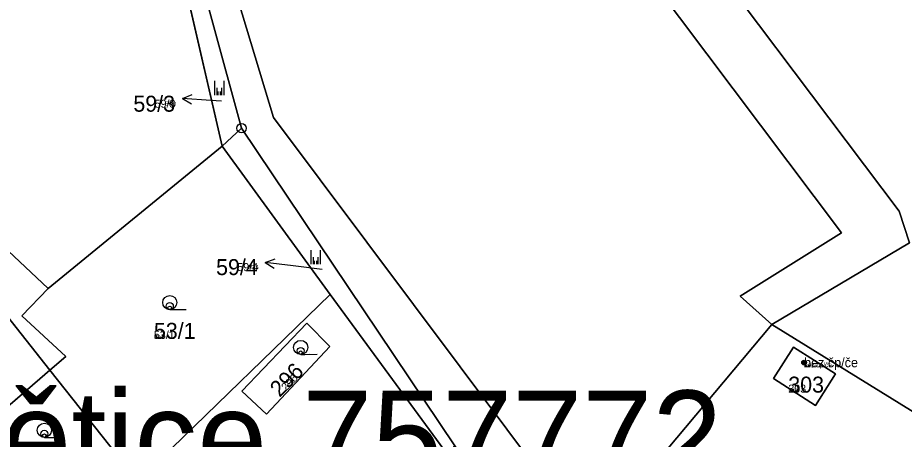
# Model space of a CAD drawing. Extents: x -759873 to -758487, y -975024 to -973516.
# Drawn here: x -759094.4 to -759000.3, y -974305.6 to -974260.8 of the extents above; entities that cross this region are included whole.
import ezdxf

# ---------------------------------------------------------------- set-up
doc = ezdxf.new("R2010")
doc.units = 0
for name, color, linetype in [('KAT_02_hranice parcel', 7, 'Continuous'), ('KAT_03_1000_st čísla parcelní', 7, 'Continuous'), ('KAT_03_1000_čísla parcelní', 7, 'Continuous'), ('KAT_03_1000_čísla popisná', 7, 'Continuous'), ('KAT_03_250_st čísla parcelní', 7, 'Continuous'), ('KAT_03_250_čísla parcelní', 7, 'Continuous'), ('KAT_03_250_čísla popisná', 7, 'Continuous'), ('KAT_03_500_st čísla parcelní', 7, 'Continuous'), ('KAT_03_500_čísla parcelní', 7, 'Continuous'), ('KAT_03_500_čísla popisná', 7, 'Continuous'), ('KAT_05_1000_značky kultur', 7, 'Continuous'), ('KAT_05_250_značky kultur', 7, 'Continuous'), ('KAT_05_500_značky kultur', 7, 'Continuous'), ('KAT_07_1000_značky budov', 7, 'Continuous'), ('KAT_07_250_značky budov', 7, 'Continuous'), ('KAT_07_500_značky budov', 7, 'Continuous'), ('KAT_11_značky bodu BP', 7, 'Continuous'), ('KAT_12_pomocná šipka', 7, 'Continuous'), ('KAT_13_popis', 7, 'Continuous'), ('KAT_14_plocha_budovy', 7, 'Continuous'), ('KAT_14_plocha_pozemek', 7, 'Continuous')]:
    doc.layers.add(name, color=color, linetype=linetype)

msp = doc.modelspace()

# ---------------------------------------------------------------- linework, layer by layer
at = {"layer": 'KAT_02_hranice parcel'}
for p, q in [((-759072.72, -974274.42), (-759081.12, -974237.92)), ((-759072.72, -974274.42), (-759070.66, -974272.52)), ((-759070.66, -974272.52), (-759048.01, -974306.32)), ((-759091.19, -974289.59), (-759072.72, -974274.42)), ((-759061.26, -974290.22), (-759072.72, -974274.42)), ((-759091.02, -974298.25), (-759100.58, -974286.17)), ((-759061.26, -974290.22), (-759079.26, -974307.73)), ((-759048.78, -974307.23), (-759061.26, -974290.22)), ((-759014.33, -974293.41), (-758997.18, -974304.01)), ((-759098.18, -974304.42), (-759091.02, -974298.25)), ((-759083.84, -974307.33), (-759091.02, -974298.25))]:
    msp.add_line(p, q, dxfattribs=at)
for points in [[(-759057.23, -974110.82), (-759070.93, -974124.94), (-759074.88, -974130.5), (-759080.81, -974167.04), (-759083.49, -974196.85), (-759080.01, -974222.92), (-759077.81, -974236.38), (-759067.25, -974271.4), (-759032.56, -974317.79)], [(-759057.23, -974110.82), (-759060.75, -974132.98), (-759061.42, -974162.34), (-759060.12, -974196.25), (-759049.48, -974222.24), (-759032.75, -974249.27), (-759006.93, -974283.66), (-759017.69, -974290.39), (-759014.33, -974293.41)], [(-759081.12, -974237.92), (-759079.79, -974238.96), (-759070.66, -974272.52)], [(-759033.4, -974238.15), (-759026.91, -974246.64), (-759000.81, -974281.35), (-758999.72, -974284.7), (-759014.33, -974293.41)], [(-759123.38, -974266.06), (-759120.2, -974262.27), (-759091.19, -974289.59)], [(-759091.19, -974289.59), (-759093.99, -974292.47), (-759089.32, -974296.79), (-759091.02, -974298.25)], [(-759061.29, -974295.76), (-759068, -974302.93), (-759070.62, -974300.51), (-759063.73, -974293.25), (-759061.29, -974295.76)], [(-759014.33, -974293.41), (-759025.5, -974306.76), (-759032.56, -974317.79)], [(-759007.55, -974298.66), (-759009.69, -974302.02), (-759014.16, -974299.16), (-759012.02, -974295.81), (-759007.55, -974298.66)]]:
    msp.add_lwpolyline(points, dxfattribs=at)
at = {"layer": 'KAT_03_1000_čísla popisná'}
msp.add_circle((-759010.9, -974297.45), 0.25, dxfattribs=at)
at = {"layer": 'KAT_03_250_čísla popisná'}
msp.add_circle((-759010.9, -974297.45), 0.0625, dxfattribs=at)
at = {"layer": 'KAT_03_500_čísla popisná'}
msp.add_circle((-759010.9, -974297.45), 0.125, dxfattribs=at)
at = {"layer": 'KAT_05_1000_značky kultur'}
for p, q in [((-759073.511, -974268.99), (-759073.511, -974267.49)), ((-759072.51, -974268.99), (-759072.51, -974267.49)), ((-759063.281, -974287), (-759063.281, -974285.5)), ((-759062.28, -974287), (-759062.28, -974285.5)), ((-759078.283, -974291.82), (-759076.533, -974291.82)), ((-759064.363, -974296.59), (-759062.613, -974296.559)), ((-759091.603, -974305.41), (-759089.853, -974305.41))]:
    msp.add_line(p, q, dxfattribs=at)
for centre in [(-759078.283, -974291.07), (-759064.376, -974295.84), (-759091.603, -974304.66)]:
    msp.add_circle(centre, 0.75, dxfattribs=at)
at = {"layer": 'KAT_05_250_značky kultur'}
for p, q in [((-759073.128, -974268.99), (-759073.128, -974268.615)), ((-759072.878, -974268.99), (-759072.878, -974268.615)), ((-759062.898, -974287), (-759062.898, -974286.625)), ((-759062.647, -974287), (-759062.647, -974286.625)), ((-759078.288, -974291.82), (-759077.851, -974291.82)), ((-759064.368, -974296.59), (-759063.931, -974296.582)), ((-759091.608, -974305.41), (-759091.171, -974305.41))]:
    msp.add_line(p, q, dxfattribs=at)
for centre in [(-759078.288, -974291.632), (-759064.371, -974296.402), (-759091.608, -974305.222)]:
    msp.add_circle(centre, 0.187, dxfattribs=at)
at = {"layer": 'KAT_05_500_značky kultur'}
for p, q in [((-759073.255, -974268.99), (-759073.255, -974268.24)), ((-759072.755, -974268.99), (-759072.755, -974268.24)), ((-759063.025, -974287), (-759063.025, -974286.25)), ((-759062.525, -974287), (-759062.525, -974286.25)), ((-759078.287, -974291.82), (-759077.412, -974291.82)), ((-759064.367, -974296.59), (-759063.492, -974296.574)), ((-759091.606, -974305.41), (-759090.731, -974305.41))]:
    msp.add_line(p, q, dxfattribs=at)
for centre in [(-759078.286, -974291.445), (-759064.373, -974296.215), (-759091.606, -974305.035)]:
    msp.add_circle(centre, 0.375, dxfattribs=at)
at = {"layer": 'KAT_07_1000_značky budov'}
msp.add_circle((-759010.907, -974297.449), 0.175, dxfattribs=at)
at = {"layer": 'KAT_07_250_značky budov'}
msp.add_circle((-759010.902, -974297.45), 0.0437, dxfattribs=at)
at = {"layer": 'KAT_07_500_značky budov'}
msp.add_circle((-759010.903, -974297.45), 0.0875, dxfattribs=at)
at = {"layer": 'KAT_11_značky bodu BP'}
for radius in [0.5, 0.0303]:
    msp.add_circle((-759070.66, -974272.52), radius, dxfattribs=at)
at = {"layer": 'KAT_12_pomocná šipka'}
for p, q in [((-759076.924, -974269.371), (-759075.89, -974268.941)), ((-759073.93, -974269.58), (-759076.924, -974269.371)), ((-759076.924, -974269.371), (-759075.96, -974269.94)), ((-759072.79, -974269.66), (-759073.93, -974269.58)), ((-759068.139, -974286.804), (-759067.084, -974286.429)), ((-759065.16, -974287.17), (-759068.139, -974286.804)), ((-759068.139, -974286.804), (-759067.206, -974287.423)), ((-759062.09, -974287.54), (-759065.16, -974287.17))]:
    msp.add_line(p, q, dxfattribs=at)
at = {"layer": 'KAT_14_plocha_budovy'}
msp.add_lwpolyline([(-759014.16, -974299.16), (-759009.69, -974302.02), (-759007.55, -974298.66), (-759012.02, -974295.81)], close=True, dxfattribs=at)
at = {"layer": 'KAT_14_plocha_pozemek'}
for points in [[(-758984.12, -974076.91), (-759010.79, -974116.64), (-759007.07, -974119.22), (-759009.9, -974123.16), (-759045.17, -974103.85), (-759057.23, -974110.82), (-759057.79, -974134.47), (-759058.26, -974162.28), (-759056.91, -974183.77), (-759044.48, -974221.35), (-759033.4, -974238.15), (-759026.91, -974246.64), (-759000.81, -974281.35), (-758999.72, -974284.7), (-759014.33, -974293.41), (-758997.18, -974304.01)], [(-759088.06, -974196.14), (-759086.81, -974208.04), (-759084.6, -974223.26), (-759081.12, -974237.92), (-759079.79, -974238.96), (-759070.66, -974272.52), (-759048.01, -974306.32), (-759035.84, -974324.49), (-759036.24, -974328.76), (-759037.74, -974344.49), (-759041.4, -974353.16), (-759035.22, -974352.69), (-759034.31, -974346.71), (-759033.62, -974342.2), (-759031.96, -974331.33), (-759032.33, -974323.02), (-759032.56, -974317.79), (-759067.25, -974271.4), (-759077.81, -974236.38), (-759080.01, -974222.92), (-759083.49, -974196.85)]]:
    msp.add_lwpolyline(points, dxfattribs=at)
for points in [[(-759077.81, -974236.38), (-759067.25, -974271.4), (-759032.56, -974317.79), (-759025.5, -974306.76), (-759014.33, -974293.41), (-759017.69, -974290.39), (-759006.93, -974283.66), (-759032.75, -974249.27), (-759049.48, -974222.24), (-759060.12, -974196.25), (-759061.42, -974162.34), (-759060.75, -974132.98), (-759057.23, -974110.82), (-759070.93, -974124.94), (-759074.88, -974130.5), (-759080.81, -974167.04), (-759083.49, -974196.85), (-759080.01, -974222.92)], [(-759060.12, -974196.25), (-759049.48, -974222.24), (-759032.75, -974249.27), (-759006.93, -974283.66), (-759017.69, -974290.39), (-759014.33, -974293.41), (-758999.72, -974284.7), (-759000.81, -974281.35), (-759026.91, -974246.64), (-759033.4, -974238.15), (-759045.51, -974222.29), (-759056.12, -974196.39), (-759056.91, -974183.77), (-759058.26, -974162.28), (-759057.79, -974134.47), (-759057.23, -974110.82), (-759060.75, -974132.98), (-759061.42, -974162.34)], [(-759072.72, -974274.42), (-759081.12, -974237.92), (-759082.54, -974240.13), (-759102.76, -974233.33), (-759134.45, -974270.58), (-759130.63, -974274.73), (-759123.38, -974266.06), (-759120.2, -974262.27), (-759091.19, -974289.59)], [(-759070.66, -974272.52), (-759079.79, -974238.96), (-759081.12, -974237.92), (-759072.72, -974274.42)], [(-759100.58, -974286.17), (-759091.02, -974298.25), (-759089.32, -974296.79), (-759093.99, -974292.47), (-759091.19, -974289.59), (-759120.2, -974262.27), (-759123.38, -974266.06), (-759114.7, -974272.79), (-759106.45, -974280.08)], [(-759048.01, -974306.32), (-759070.66, -974272.52), (-759072.72, -974274.42), (-759061.26, -974290.22), (-759048.78, -974307.23)], [(-759061.26, -974290.22), (-759072.72, -974274.42), (-759091.19, -974289.59), (-759093.99, -974292.47), (-759089.32, -974296.79), (-759091.02, -974298.25), (-759083.84, -974307.33), (-759081.67, -974310.08), (-759079.26, -974307.73)], [(-759098.18, -974304.42), (-759091.02, -974298.25), (-759100.58, -974286.17), (-759109.41, -974292.79), (-759106.6, -974295.05)], [(-759048.78, -974307.23), (-759061.26, -974290.22), (-759079.26, -974307.73), (-759078.92, -974308), (-759078.18, -974307.34), (-759074.22, -974311.83), (-759069.39, -974315.76), (-759070.15, -974316.45), (-759070.68, -974316.93), (-759071.63, -974317.79), (-759073.23, -974319.23), (-759078.17, -974323.68), (-759084.21, -974316.89), (-759085.69, -974318.34), (-759072.66, -974333.02), (-759060.22, -974319.58), (-759051.05, -974309.82)], [(-759061.29, -974295.76), (-759068, -974302.93), (-759070.62, -974300.51), (-759063.73, -974293.25)], [(-759061.29, -974295.76), (-759063.73, -974293.25), (-759070.62, -974300.51), (-759068, -974302.93)], [(-758997.18, -974304.01), (-759014.33, -974293.41), (-759025.5, -974306.76), (-759032.56, -974317.79), (-759032.33, -974323.02), (-759027, -974314.69), (-758998.23, -974316.19)], [(-759007.55, -974298.66), (-759009.69, -974302.02), (-759014.16, -974299.16), (-759012.02, -974295.81)], [(-759007.55, -974298.66), (-759012.02, -974295.81), (-759014.16, -974299.16), (-759009.69, -974302.02)], [(-759091.02, -974298.25), (-759098.18, -974304.42), (-759090.1, -974313.42), (-759083.84, -974307.33)]]:
    msp.add_lwpolyline(points, close=True, dxfattribs=at)

# ---------------------------------------------------------------- texts
at = {"layer": 'KAT_03_1000_st čísla parcelní'}
msp.add_text('303', height=1.7, dxfattribs=at).set_placement((-759012.58, -974300.65))
at = {"layer": 'KAT_03_1000_čísla parcelní'}
for s, p in [('59/3', (-759082.152, -974270.766)), ('59/4', (-759073.362, -974288.146)), ('53/1', (-759079.97, -974294.929))]:
    msp.add_text(s, height=1.7, dxfattribs=at).set_placement(p)
msp.add_text('296', height=1.7, rotation=45, dxfattribs=at).set_placement((-759066.615, -974301.207))
at = {"layer": 'KAT_03_1000_čísla popisná'}
msp.add_text('bez čp/če', height=1, dxfattribs=at).set_placement((-759010.9, -974297.95))
at = {"layer": 'KAT_03_250_st čísla parcelní'}
msp.add_text('303', height=0.425, dxfattribs=at).set_placement((-759012.58, -974300.65))
at = {"layer": 'KAT_03_250_čísla parcelní'}
for s, p in [('59/3', (-759078.767, -974270.129)), ('59/4', (-759069.983, -974287.509)), ('53/1', (-759079.97, -974294.929))]:
    msp.add_text(s, height=0.425, dxfattribs=at).set_placement(p)
msp.add_text('296', height=0.425, rotation=45, dxfattribs=at).set_placement((-759065.593, -974300.185))
at = {"layer": 'KAT_03_250_čísla popisná'}
msp.add_text('bez čp/če', height=0.25, dxfattribs=at).set_placement((-759010.9, -974297.95))
at = {"layer": 'KAT_03_500_st čísla parcelní'}
msp.add_text('303', height=0.85, dxfattribs=at).set_placement((-759012.58, -974300.65))
at = {"layer": 'KAT_03_500_čísla parcelní'}
for s, p in [('59/3', (-759079.895, -974270.341)), ('59/4', (-759071.109, -974287.721)), ('53/1', (-759079.97, -974294.929))]:
    msp.add_text(s, height=0.85, dxfattribs=at).set_placement(p)
msp.add_text('296', height=0.85, rotation=45, dxfattribs=at).set_placement((-759065.934, -974300.526))
at = {"layer": 'KAT_03_500_čísla popisná'}
msp.add_text('bez čp/če', height=0.5, dxfattribs=at).set_placement((-759010.9, -974297.95))
at = {"layer": 'KAT_13_popis'}
msp.add_text('Dobětice 757772', height=10, dxfattribs=at).set_placement((-759120.712, -974310.427))

doc.saveas('drawing.dxf')
